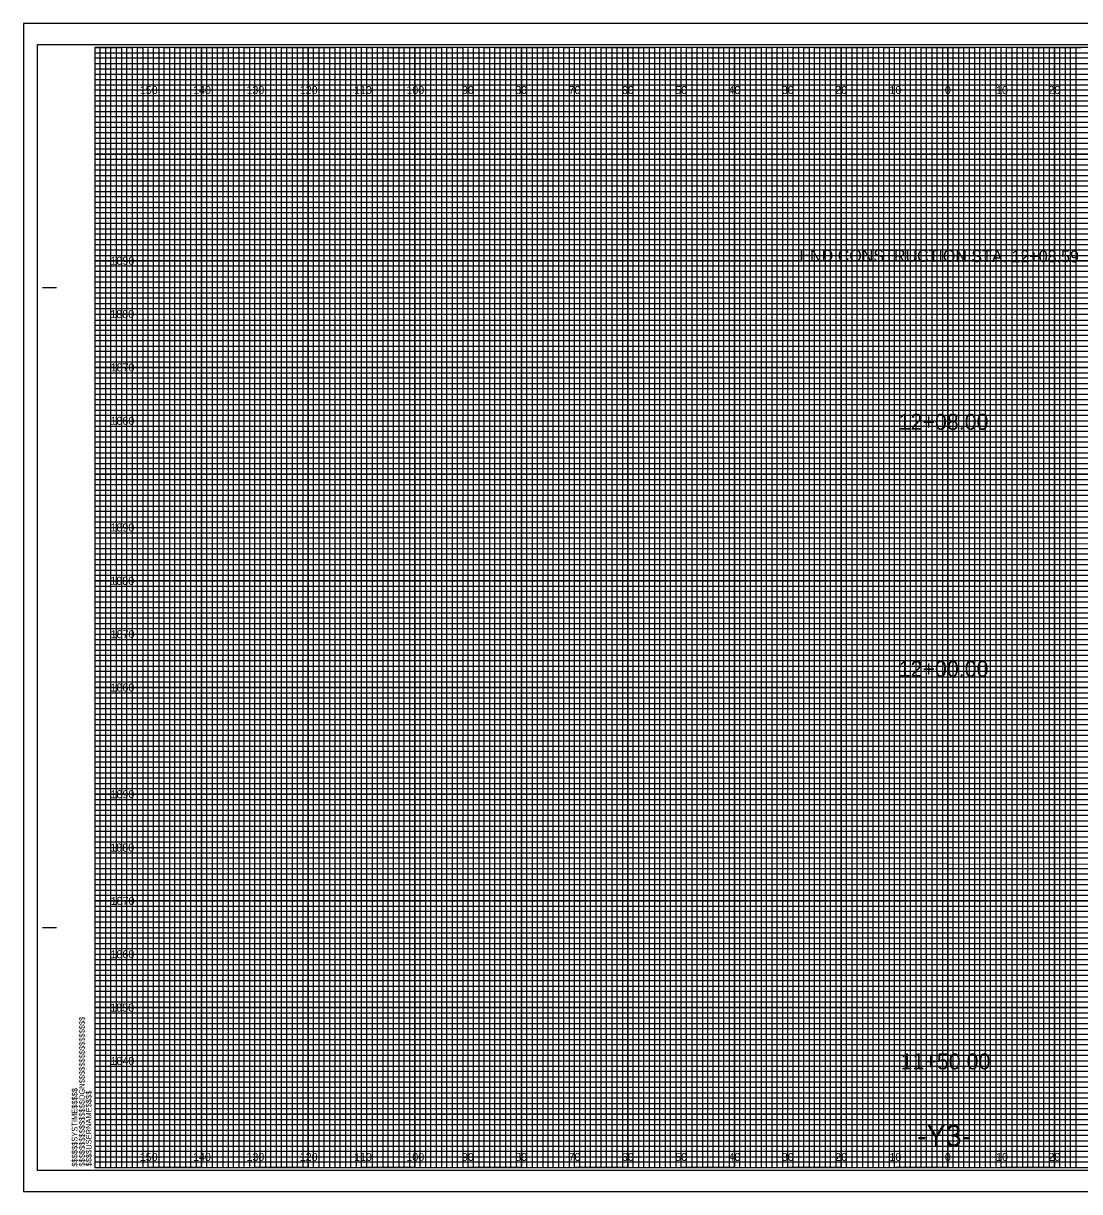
# Model space of a CAD drawing. Extents: x -13 to 323, y 216 to 434.
# Drawn here: x -13.4 to 184.7, y 215.5 to 434.5 of the extents above; entities that cross this region are included whole.
import ezdxf

# ---------------------------------------------------------------- set-up
doc = ezdxf.new("R2010")
doc.units = 0
for name, color, linetype in [('Prop XS Alignment Label', 7, 'Continuous'), ('Prop XS Elevation Labels', 7, 'Continuous'), ('Prop XS Offset Labels', 7, 'Continuous'), ('Prop XS SE Text', 7, 'Continuous'), ('Prop XS Station Labels', 7, 'Continuous'), ('Sheet Cross Section CELL', 7, 'Continuous'), ('Sheet Cross Section Grid Major CELL', 7, 'Continuous'), ('Sheet Cross Section Grid Middle CELL', 7, 'Continuous'), ('Sheet Cross Section Grid Minor 1 CELL', 7, 'Continuous'), ('Sheet Cross Section Grid Minor 2 CELL', 7, 'Continuous'), ('Sheet Cutting Line CELL', 7, 'Continuous'), ('Sheet DOT Grid CELL', 7, 'Continuous'), ('Sheet Plot Border Inside CELL', 7, 'Continuous'), ('Sheet Plot Border Outside CELL', 7, 'Continuous')]:
    doc.layers.add(name, color=color, linetype=linetype)

msp = doc.modelspace()

# ---------------------------------------------------------------- linework, layer by layer
at = {"layer": 'Sheet Cross Section CELL'}
for p, q in [((-9.8, 385), (-7.3, 385)), ((-9.7, 385), (-7.2, 385)), ((-9.8, 265), (-7.3, 265)), ((-9.7, 265), (-7.2, 265))]:
    msp.add_line(p, q, dxfattribs=at)
msp.add_lwpolyline([(320, 430), (0, 430), (0, 220), (320, 220)], close=True, dxfattribs=at)
at = {"layer": 'Sheet Cross Section Grid Major CELL'}
for p, q in [((10, 430), (0, 430)), ((10, 220), (10, 430)), ((30, 430), (20, 430)), ((20, 430), (20, 220)), ((30, 220), (30, 430)), ((50, 430), (40, 430)), ((40, 430), (40, 220)), ((50, 220), (50, 430)), ((70, 430), (60, 430)), ((60, 430), (60, 220)), ((70, 220), (70, 430)), ((90, 430), (80, 430)), ((80, 430), (80, 220)), ((90, 220), (90, 430)), ((110, 430), (100, 430)), ((100, 430), (100, 220)), ((110, 220), (110, 430)), ((130, 430), (120, 430)), ((120, 430), (120, 220)), ((130, 220), (130, 430)), ((150, 430), (140, 430)), ((140, 430), (140, 220)), ((150, 220), (150, 430)), ((170, 430), (160, 430)), ((160, 430), (160, 220)), ((170, 220), (170, 430)), ((190, 430), (180, 430)), ((180, 430), (180, 220)), ((20, 220), (10, 220)), ((40, 220), (30, 220)), ((60, 220), (50, 220)), ((80, 220), (70, 220)), ((100, 220), (90, 220)), ((120, 220), (110, 220)), ((140, 220), (130, 220)), ((160, 220), (150, 220)), ((180, 220), (170, 220))]:
    msp.add_line(p, q, dxfattribs=at)
for points in [[(0, 420), (320, 420), (320, 410), (0, 410)], [(0, 400), (320, 400), (320, 390), (0, 390)], [(0, 380), (320, 380), (320, 370), (0, 370)], [(0, 360), (320, 360), (320, 350), (0, 350)], [(0, 340), (320, 340), (320, 330), (0, 330)], [(0, 320), (320, 320), (320, 310), (0, 310)], [(0, 300), (320, 300), (320, 290), (0, 290)], [(0, 280), (320, 280), (320, 270), (0, 270)], [(0, 260), (320, 260), (320, 250), (0, 250)], [(0, 240), (320, 240), (320, 230), (0, 230)]]:
    msp.add_lwpolyline(points, dxfattribs=at)
at = {"layer": 'Sheet Cross Section Grid Middle CELL'}
for points in [[(0, 430), (5, 430), (5, 220), (15, 220), (15, 430), (25, 430), (25, 220), (35, 220), (35, 430), (45, 430), (45, 220), (55, 220), (55, 430), (65, 430), (65, 220), (75, 220), (75, 430), (85, 430), (85, 220), (95, 220), (95, 430), (105, 430), (105, 220), (115, 220), (115, 430), (125, 430), (125, 220), (135, 220), (135, 430), (145, 430), (145, 220), (155, 220), (155, 430), (165, 430), (165, 220), (175, 220), (175, 430), (185, 430)], [(0, 425), (275, 425)], [(0, 405), (320, 405), (320, 415), (0, 415)], [(0, 385), (320, 385), (320, 395), (0, 395)], [(0, 365), (320, 365), (320, 375), (0, 375)], [(0, 345), (320, 345), (320, 355), (0, 355)], [(0, 325), (320, 325), (320, 335), (0, 335)], [(0, 305), (320, 305), (320, 315), (0, 315)], [(0, 285), (320, 285), (320, 295), (0, 295)], [(0, 265), (320, 265), (320, 275), (0, 275)], [(0, 245), (320, 245), (320, 255), (0, 255)], [(0, 225), (320, 225), (320, 235), (0, 235)]]:
    msp.add_lwpolyline(points, dxfattribs=at)
at = {"layer": 'Sheet Cross Section Grid Minor 1 CELL'}
for p, q in [((0, 429), (260, 429)), ((260, 427.98), (0, 427.98)), ((0, 427.98), (0, 427)), ((0, 427), (260, 427)), ((260, 425.89), (0, 425.89)), ((0, 425.89), (0, 424)), ((0, 424), (320, 424))]:
    msp.add_line(p, q, dxfattribs=at)
for points in [[(0, 423), (270, 423), (320, 423), (320, 422), (0, 422)], [(0, 421), (320, 421), (320, 419), (0, 419)], [(0, 418), (320, 418), (320, 417), (0, 416.98)], [(0, 416), (320, 416), (320, 414), (0, 414)], [(0, 413), (320, 413), (320, 412), (0, 412)], [(0, 411), (320, 411), (320, 409), (0, 409)], [(0, 408), (320, 408), (320, 407), (0, 407)], [(0, 406), (320, 406), (320, 404), (0, 404)], [(0, 403), (320, 403), (320, 402), (0, 402)], [(0, 401), (320, 401), (320, 399), (0, 399)], [(0, 398), (320, 398), (320, 397), (0, 397)], [(0, 396), (320, 396), (320, 393.95), (320, 393), (320, 392), (0, 392)], [(0, 394), (320, 394), (320, 393), (0, 393)], [(0, 391), (320, 391), (320, 389), (0, 389.03)], [(0, 389.03), (320, 389), (320, 388), (0, 388)], [(0, 387), (320, 387), (320, 386), (0, 386)], [(0, 384), (320, 384), (320, 383), (0, 383)], [(0, 382), (320, 382), (320, 381), (0, 381)], [(-0.07, 378.89), (320, 378.89), (320, 377.88), (-0.07, 377.88)], [(0, 377), (320, 377), (320, 376), (0, 376)], [(0, 374), (320, 374), (320, 373), (0, 373)], [(0, 372), (320, 372), (320, 371), (0, 371)], [(0, 369), (320, 369), (320, 368), (0, 368)], [(0, 367), (320, 367), (320, 366), (0, 366)], [(0, 364), (320, 364), (320, 363), (0, 363)], [(0, 362), (320, 362), (320, 361), (0, 361)], [(0, 359), (320, 359), (319.99, 357.98), (0, 358)], [(0, 357), (320, 357), (320, 356), (0, 356)], [(0, 354), (320, 354), (320, 353), (0, 353)], [(0, 352), (320, 352), (320, 351), (0, 351)], [(0, 349), (320, 349), (320, 348), (0, 348)], [(0, 347), (320, 347), (320, 346), (0, 346)], [(0, 344), (320, 344), (320, 343), (0, 343)], [(0, 342), (320, 342), (320, 341), (0, 341)], [(0, 339), (320, 339), (320, 338), (0, 338)], [(0, 336.99), (320.07, 336.91), (320, 336), (0, 336)], [(0, 334), (320, 334), (320, 333), (0, 333)], [(0, 332), (320, 332), (320, 331), (0, 331)], [(0, 329), (320, 329), (320, 328), (0, 328)], [(0, 327), (320, 327), (320, 326), (0, 326)], [(0, 324), (320, 324), (320, 323), (0, 323)], [(0, 322), (320, 322), (320, 321), (0, 321)], [(0, 319), (320, 319), (320, 318), (0, 318)], [(0, 317), (320, 317), (320, 316), (0, 316)], [(0, 314), (320, 314), (320, 313), (0, 313)], [(0, 312), (320, 312), (320, 311), (0, 311)], [(0, 309), (320, 309), (320, 308), (0, 308)], [(0, 307), (320, 307), (320, 306), (0, 306)], [(0, 304), (320, 304), (320, 303), (0, 303)], [(0, 302), (320, 302), (320, 301), (0, 301)], [(0, 299), (320, 299), (319.99, 297.98), (0, 298)], [(0, 297), (320, 297), (320, 296), (0, 296)], [(0, 294), (320, 294), (320, 293), (0, 293)], [(0, 292), (320, 292), (320, 291), (0, 291)], [(0, 289), (320, 289), (320, 288), (0, 288)], [(0, 287), (320, 287), (320, 286), (0, 286)], [(0, 284), (320, 284), (320, 283), (0, 283)], [(0, 282), (320, 282), (320, 281), (0, 281)], [(0, 279), (320, 279), (320, 278), (0, 278)], [(0, 276.99), (320.07, 276.91), (320, 276), (0, 276)], [(0, 274), (320, 274), (320, 273), (0, 273)], [(0, 272), (320, 272), (320, 271), (0, 271)], [(0, 269), (320, 269), (320, 268), (0, 268)], [(0, 267), (320, 267), (320, 266), (0, 266)], [(0, 264), (320, 264), (320, 263), (0, 263)], [(0, 262), (320, 262), (320, 261), (0, 261)], [(0, 259), (320, 259), (320, 258), (0, 258)], [(0, 257), (320, 257), (320, 256), (0, 256)], [(0, 254), (320, 254), (320, 253), (0, 253)], [(0, 252), (320, 252), (320, 251), (0, 251)], [(0, 249), (320, 249), (320, 248), (0, 248)], [(0, 247), (320, 247), (320, 246), (0, 246)], [(0, 244), (320, 244), (320, 243), (0, 243)], [(0, 242), (320, 242), (320, 241), (0, 241)], [(0, 239), (320, 239), (320, 238), (0, 238)], [(0, 237), (320, 237), (320, 236), (0, 236)], [(0, 234), (320, 234), (320, 233), (0, 233)], [(0, 232), (320, 232), (320, 231), (0, 231)], [(0, 229), (320, 229), (320, 228), (0, 228)], [(0, 227), (320, 227), (320, 226), (0, 226)], [(0, 224), (320, 224), (320, 223), (0, 223)], [(0, 222), (320, 222), (320, 221), (0, 221)]]:
    msp.add_lwpolyline(points, dxfattribs=at)
at = {"layer": 'Sheet Cross Section Grid Minor 2 CELL'}
for points in [[(0, 220), (1, 220), (1, 430), (2, 430), (2, 220)], [(2, 220), (3, 220), (3, 430), (4, 430), (4, 220)], [(5, 220), (6, 220), (6, 430), (7, 430), (7, 220)], [(7, 220), (8, 220), (8, 430), (9, 430), (9, 220)], [(10, 220), (11, 220), (11, 430), (12, 430), (12, 220)], [(12, 220), (13, 220), (13, 430), (14, 430), (14, 220)], [(15, 220), (16, 220), (16, 430), (17, 430), (17, 220)], [(17, 220), (18, 220), (18, 430), (19, 430), (19, 220)], [(20, 220), (21, 220), (21, 430), (22, 430), (22, 220)], [(22, 220), (23, 220), (23, 430), (24, 430), (24, 220)], [(25, 220), (26, 220), (26, 430), (27, 430), (27, 220)], [(27, 220), (28, 220), (28, 430), (29, 430), (29, 220)], [(30, 220), (31, 220), (31, 430), (32, 430), (32, 220)], [(32, 220), (33, 220), (33, 430), (34, 430), (34, 220)], [(35, 220), (36, 220), (36, 430), (37, 430), (37, 220)], [(37, 220), (38, 220), (38, 430), (39, 430), (39, 220)], [(40, 220), (41, 220), (41, 430), (42, 430), (42, 220)], [(42, 220), (43, 220), (43, 430), (44, 430), (44, 220)], [(45, 220), (46, 220), (46, 430), (47, 430), (47, 220)], [(47, 220), (48, 220), (48, 430), (49, 430), (49, 220)], [(50, 220), (51, 220), (51, 430), (52, 430), (52, 220)], [(52, 220), (53, 220), (53, 430), (54, 430), (54, 220)], [(55, 220), (56, 220), (56, 430), (57, 430), (57, 220)], [(57, 220), (58, 220), (58, 430), (59, 430), (59, 220)], [(60, 220), (61, 220), (61, 430), (62, 430), (62, 220)], [(62, 220), (63, 220), (63, 430), (64, 430), (64, 220)], [(65, 220), (66, 220), (66, 430), (67, 430), (67, 220)], [(67, 220), (68, 220), (68, 430), (69, 430), (69, 220)], [(70, 220), (71, 220), (71, 430), (72, 430), (72, 220)], [(72, 220), (73, 220), (73, 430), (74, 430), (74, 220)], [(75, 220), (76, 220), (76, 430), (77, 430), (77, 220)], [(77, 220), (78, 220), (78, 430), (79, 430), (79, 220)], [(80, 220), (81, 220), (81, 430), (82, 430), (82, 220)], [(82, 220), (83, 220), (83, 430), (84, 430), (84, 220)], [(85, 220), (86, 220), (86, 430), (87, 430), (87, 220)], [(87, 220), (88, 220), (88, 430), (89, 430), (89, 220)], [(90, 220), (91, 220), (91, 430), (92, 430), (92, 220)], [(92, 220), (93, 220), (93, 430), (94, 430), (94, 220)], [(95, 220), (96, 220), (96, 430), (97, 430), (97, 220)], [(97, 220), (98, 220), (98, 430), (99, 430), (99, 220)], [(100, 220), (101, 220), (101, 430), (102, 430), (102, 220)], [(102, 220), (103, 220), (103, 430), (104, 430), (104, 220)], [(105, 220), (106, 220), (106, 430), (107, 430), (107, 220)], [(107, 220), (108, 220), (108, 430), (109, 430), (109, 220)], [(110, 220), (111, 220), (111, 430), (112, 430), (112, 220)], [(112, 220), (113, 220), (113, 430), (114, 430), (114, 220)], [(115, 220), (116, 220), (116, 430), (117, 430), (117, 220)], [(117, 220), (118, 220), (118, 430), (119, 430), (119, 220)], [(120, 220), (121, 220), (121, 430), (122, 430), (122, 220)], [(122, 220), (123, 220), (123, 430), (124, 430), (124, 220)], [(125, 220), (126, 220), (126, 430), (127, 430), (127, 220)], [(127, 220), (128, 220), (128, 430), (129, 430), (129, 220)], [(130, 220), (131, 220), (131, 430), (132, 430), (132, 220)], [(132, 220), (133, 220), (133, 430), (134, 430), (134, 220)], [(135, 220), (136, 220), (136, 430), (137, 430), (137, 220)], [(137, 220), (138, 220), (138, 430), (139, 430), (139, 220)], [(140, 220), (141, 220), (141, 430), (142, 430), (142, 220)], [(142, 220), (143, 220), (143, 430), (144, 430), (144, 220)], [(145, 220), (146, 220), (146, 430), (147, 430), (147, 220)], [(147, 220), (148, 220), (148, 430), (149, 430), (149, 220)], [(150, 220), (151, 220), (151, 430), (152, 430), (152, 220)], [(152, 220), (153, 220), (153, 430), (154, 430), (154, 220)], [(155, 220), (156, 220), (156, 430), (157, 430), (157, 220)], [(157, 220), (158, 220), (158, 430), (159, 430), (159, 220)], [(160, 220), (161, 220), (161, 430), (162, 430), (162, 220)], [(162, 220), (163, 220), (163, 430), (164, 430), (164, 220)], [(165, 220), (166, 220), (166, 430), (167, 430), (167, 220)], [(167, 220), (168, 220), (168, 430), (169, 430), (169, 220)], [(170, 220), (171, 220), (171, 430), (172, 430), (172, 220)], [(172, 220), (173, 220), (173, 430), (174, 430), (174, 220)], [(175, 220), (176, 220), (176, 430), (177, 430), (177, 220)], [(177, 220), (178, 220), (178, 430), (179, 430), (179, 220)], [(180, 220), (181, 220), (181, 430), (182, 430), (182, 220)], [(182, 220), (183, 220), (183, 430), (184, 430), (184, 220)]]:
    msp.add_lwpolyline(points, dxfattribs=at)
at = {"layer": 'Sheet Cutting Line CELL'}
for p, q in [((323.3, 434.5), (-13.4, 434.5)), ((-13.4, 434.5), (-13.4, 215.5)), ((-13.4, 215.5), (323.3, 215.5))]:
    msp.add_line(p, q, dxfattribs=at)
at = {"layer": 'Sheet DOT Grid CELL'}
for p, q in [((10, 220), (10, 430)), ((20, 220), (20, 430)), ((30, 220), (30, 430)), ((40, 220), (40, 430)), ((50, 220), (50, 430)), ((60, 220), (60, 430)), ((70, 220), (70, 430)), ((80, 220), (80, 430)), ((90, 220), (90, 430)), ((100, 220), (100, 430)), ((110, 220), (110, 430)), ((120, 220), (120, 430)), ((130, 220), (130, 430)), ((140, 220), (140, 430)), ((150, 220), (150, 430)), ((160, 220), (160, 430)), ((170, 220), (170, 430)), ((180, 220), (180, 430)), ((0, 420), (320, 420)), ((0, 410), (320, 410)), ((0, 400), (320, 400)), ((0, 390), (320, 390)), ((0, 380), (320, 380)), ((0, 370), (320, 370)), ((0, 360), (320, 360)), ((0, 350), (320, 350)), ((0, 340), (320, 340)), ((0, 330), (320, 330)), ((0, 320), (320, 320)), ((0, 310), (320, 310)), ((0, 300), (320, 300)), ((0, 290), (320, 290)), ((0, 280), (320, 280)), ((0, 270), (320, 270)), ((0, 260), (320, 260)), ((0, 250), (320, 250)), ((0, 240), (320, 240)), ((0, 230), (320, 230))]:
    msp.add_line(p, q, dxfattribs=at)
at = {"layer": 'Sheet Plot Border Inside CELL'}
msp.add_lwpolyline([(-10.8, 219.5), (322.4, 219.5), (322.4, 430.5), (-10.8, 430.5)], close=True, dxfattribs=at)
at = {"layer": 'Sheet Plot Border Outside CELL'}
msp.add_lwpolyline([(-13.4, 215.5), (323.3, 215.5), (323.3, 434.5), (-13.4, 434.5)], close=True, dxfattribs=at)

# ---------------------------------------------------------------- texts
at = {"layer": 'Prop XS Alignment Label'}
msp.add_text('-Y3-', height=4, dxfattribs=at).set_placement((154.25, 224))
at = {"layer": 'Prop XS Elevation Labels'}
for s, p in [('1890', (2.95, 389.25)), ('1880', (2.92, 379.25)), ('1870', (2.98, 369.25)), ('1860', (2.95, 359.25)), ('1890', (2.95, 339.25)), ('1880', (2.92, 329.25)), ('1870', (2.98, 319.25)), ('1860', (2.95, 309.25)), ('1890', (2.95, 289.25)), ('1880', (2.92, 279.25)), ('1870', (2.98, 269.25)), ('1860', (2.95, 259.25)), ('1850', (2.9, 249.25)), ('1840', (2.95, 239.25))]:
    msp.add_text(s, height=1.5, dxfattribs=at).set_placement(p)
at = {"layer": 'Prop XS Offset Labels'}
for s, p in [('150', (8.44, 421.25)), ('140', (18.44, 421.25)), ('130', (28.44, 421.25)), ('120', (38.44, 421.25)), ('110', (48.62, 421.25)), ('100', (58.44, 421.25)), ('90', (68.86, 421.25)), ('80', (78.86, 421.25)), ('70', (88.86, 421.25)), ('60', (98.86, 421.25)), ('50', (108.86, 421.25)), ('40', (118.86, 421.25)), ('30', (128.86, 421.25)), ('20', (138.86, 421.25)), ('10', (149.04, 421.25)), ('0', (159.45, 421.25)), ('0', (159.45, 421.25)), ('10', (169.04, 421.25)), ('20', (178.86, 421.25)), ('150', (8.44, 221.25)), ('140', (18.44, 221.25)), ('130', (28.44, 221.25)), ('120', (38.44, 221.25)), ('110', (48.62, 221.25)), ('100', (58.44, 221.25)), ('90', (68.86, 221.25)), ('80', (78.86, 221.25)), ('70', (88.86, 221.25)), ('60', (98.86, 221.25)), ('50', (108.86, 221.25)), ('40', (118.86, 221.25)), ('30', (128.86, 221.25)), ('20', (138.86, 221.25)), ('10', (149.04, 221.25)), ('0', (159.45, 221.25)), ('0', (159.45, 221.25)), ('10', (169.04, 221.25)), ('20', (178.86, 221.25))]:
    msp.add_text(s, height=1.5, dxfattribs=at).set_placement(p)
at = {"layer": 'Prop XS SE Text'}
msp.add_text('END CONSTRUCTION STA. 12+08.59', height=2.25, rotation=359.7978, dxfattribs=at).set_placement((132.15, 389.87))
at = {"layer": 'Prop XS Station Labels'}
for s, p in [('12+08.00', (150.77, 358.32)), ('12+00.00', (150.77, 312)), ('11+50.00', (151.13, 238.42))]:
    msp.add_text(s, height=3, dxfattribs=at).set_placement(p)
at = {"layer": 'Sheet Cross Section CELL'}
for s, p in [('$$$$$$$$$$$$$$$$DGN$$$$$$$$$$$$$$$$', (-1.88, 220.18)), ('$$$$$$SYSTIME$$$$$', (-3.26, 220.18)), ('$$$$USERNAME$$$$', (-0.62, 220.23))]:
    msp.add_text(s, height=1.05, rotation=90, dxfattribs=at).set_placement(p)

doc.saveas('drawing.dxf')
